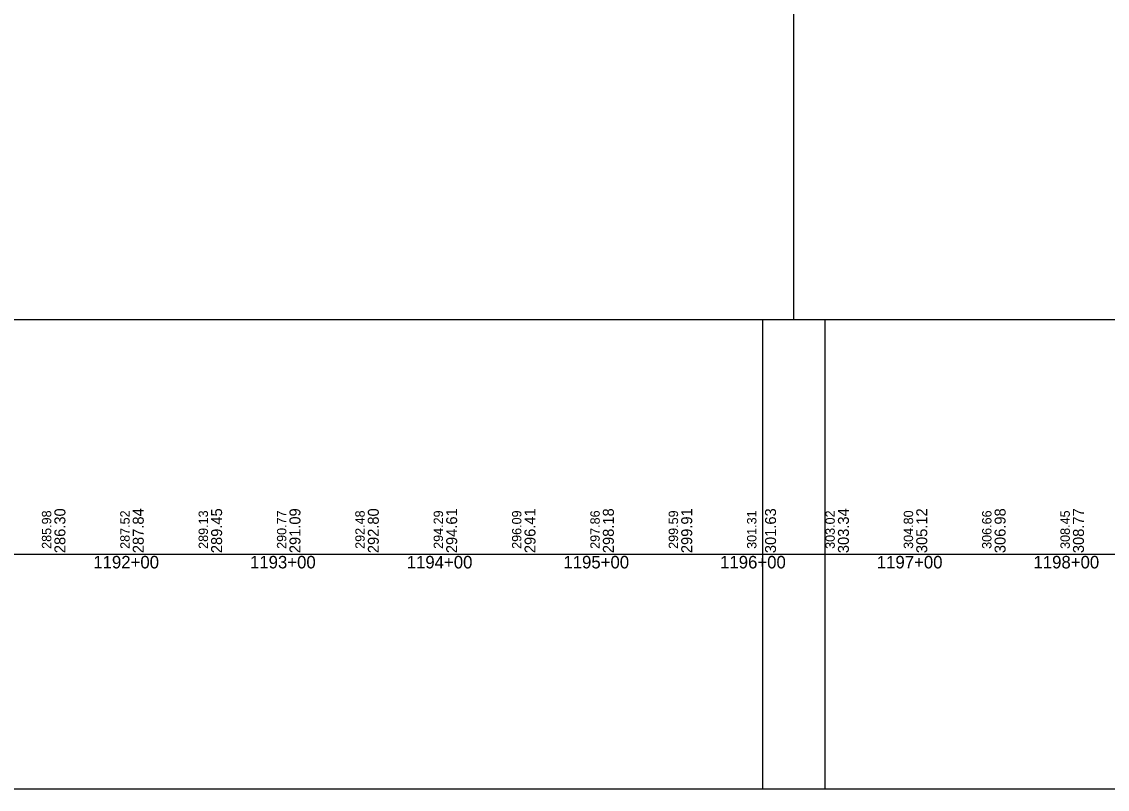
# Model space of a CAD drawing. Extents: x 2898 to 49495, y -15038 to -13538.
# Drawn here: x 8483 to 9176, y -15038 to -14548 of the extents above; entities that cross this region are included whole.
import ezdxf

# ---------------------------------------------------------------- set-up
doc = ezdxf.new("R2010")
doc.units = 0
for name, color, linetype in [('RD_DDB_StaTX', 7, 'Continuous'), ('RD_DDB_StripGrade', 7, 'Continuous'), ('RD_GPK_Profile_Cell', 7, 'Continuous'), ('RD_SHT_ShtClip', 7, 'Continuous')]:
    doc.layers.add(name, color=color, linetype=linetype)

msp = doc.modelspace()

# ---------------------------------------------------------------- linework, layer by layer
at = {"layer": 'RD_GPK_Profile_Cell'}
msp.add_line((2976.05, -14888.47), (48721.13, -14888.47), dxfattribs=at)
at = {"layer": 'RD_SHT_ShtClip'}
for points in [[(8976.22, -14738.47), (8976.22, -14238.47), (8976.22, -14238.47), (7476.38, -14238.47), (7476.38, -14738.47)], [(7456.38, -14738.47), (8996.05, -14738.47), (8996.05, -15038.47), (7456.38, -15038.47)], [(8956.38, -14738.47), (10496.05, -14738.47), (10496.05, -15038.47), (8956.38, -15038.47)]]:
    msp.add_lwpolyline(points, close=True, dxfattribs=at)

# ---------------------------------------------------------------- texts
at = {"layer": 'RD_DDB_StaTX'}
for s, p in [('1192+00', (8529.18, -14897.47)), ('1193+00', (8629.18, -14897.47)), ('1194+00', (8729.18, -14897.47)), ('1195+00', (8829.18, -14897.47)), ('1196+00', (8929.18, -14897.47)), ('1197+00', (9029.18, -14897.47)), ('1198+00', (9129.18, -14897.47))]:
    msp.add_text(s, height=8, dxfattribs=at).set_placement(p)
at = {"layer": 'RD_DDB_StripGrade'}
for s, height, p in [('286.30', 7, (8511.38, -14887.72)), ('287.84', 7, (8561.38, -14887.72)), ('289.45', 7, (8611.38, -14887.72)), ('291.09', 7, (8661.38, -14887.72)), ('292.80', 7, (8711.38, -14887.72)), ('294.61', 7, (8761.38, -14887.72)), ('296.41', 7, (8811.38, -14887.72)), ('298.18', 7, (8861.38, -14887.72)), ('299.91', 7, (8911.38, -14887.72)), ('301.63', 7, (8964.88, -14887.72)), ('303.34', 7, (9011.38, -14887.72)), ('305.12', 7, (9061.38, -14887.72)), ('306.98', 7, (9111.38, -14887.72)), ('308.77', 7, (9161.38, -14887.72)), ('285.98', 6, (8502.38, -14884.98)), ('287.52', 6, (8552.38, -14884.98)), ('289.13', 6, (8602.38, -14884.98)), ('290.77', 6, (8652.38, -14884.98)), ('292.48', 6, (8702.38, -14884.98)), ('294.29', 6, (8752.38, -14884.98)), ('296.09', 6, (8802.38, -14884.98)), ('297.86', 6, (8852.38, -14884.98)), ('299.59', 6, (8902.38, -14884.98)), ('301.31', 6, (8952.38, -14884.98)), ('303.02', 6, (9002.38, -14884.98)), ('304.80', 6, (9052.38, -14884.98)), ('306.66', 6, (9102.38, -14884.98)), ('308.45', 6, (9152.38, -14884.98))]:
    msp.add_text(s, height=height, rotation=90, dxfattribs=at).set_placement(p)

doc.saveas('drawing.dxf')
